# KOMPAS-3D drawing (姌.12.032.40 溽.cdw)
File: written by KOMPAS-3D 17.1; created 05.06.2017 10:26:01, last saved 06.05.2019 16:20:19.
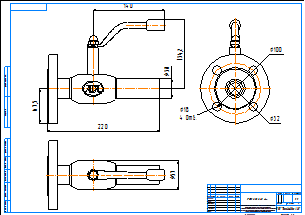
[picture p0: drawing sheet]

Sheet 1: A2, landscape

Title block, sheet 1: name: КШ.12.032.40 фс; material: Внимание! Данный продукт является объектом авторского права ООО «Торговый Дом АДЛ». / Запрещается изменение, копирование, распространение / (в том числе путем копирования на другие сайты и ресурсы в Интернете) / или любое иное использование информации и объектов без предварительного / согласия правообладателя (ООО «Торговый Дом АДЛ»).; sheets: 1; organisation: ООО "Торговый дом АДЛ"; sheet format: A2; stored path: C:\Users\kka\KOMPAS_Work\Модели кранов для исследований\Все краники\Редуцированный резьба-сварка ШК БИВАЛ\КШ.02.015.40 рс.cdw

Views: Вид 1, Проекционный вид 2, Проекционный вид 3
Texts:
  Klimkovich
  ADL
Dimensions and other numbers on the sheet: 140; 38; 220; 134,2; 67,5; 100; 32; 18; 4 Отв.; 57; 1:1; 1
